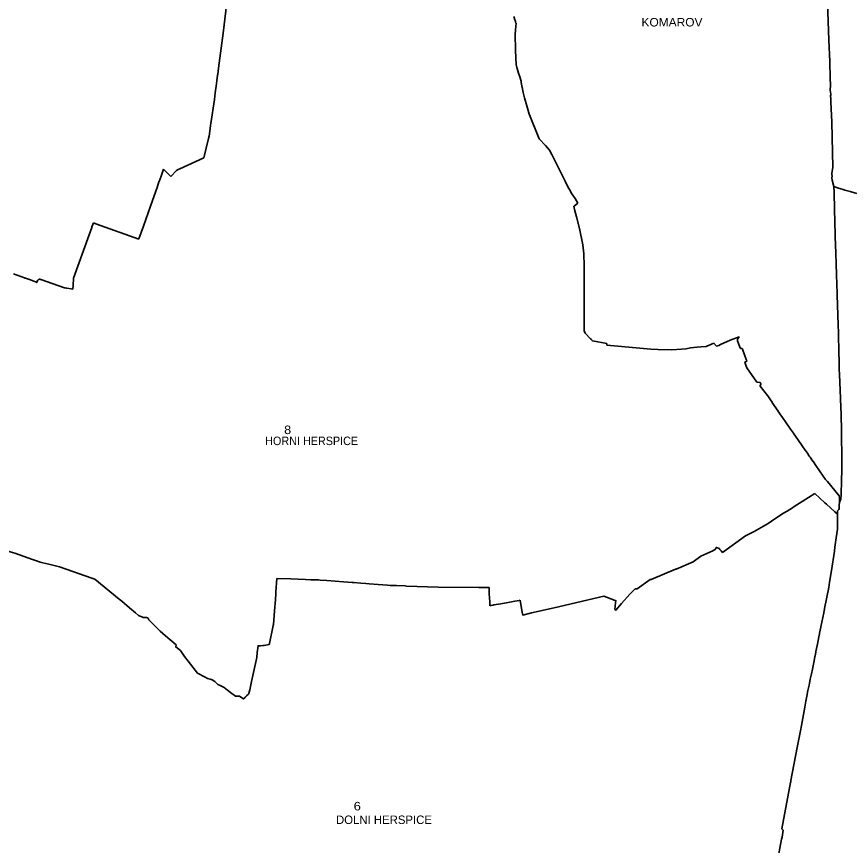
# Model space of a CAD drawing. Extents: x -610940 to -588976, y -1170376 to -1149800.
# Drawn here: x -599073 to -596623, y -1165505 to -1163066 of the extents above; entities that cross this region are included whole.
import ezdxf

# ---------------------------------------------------------------- set-up
doc = ezdxf.new("R2010")
doc.units = 0
doc.header["$LTSCALE"] = 10
doc.layers.add('54', color=7, linetype='Continuous', lineweight=35)
doc.layers.add('55', color=7, linetype='Continuous')
doc.layers.add('56', color=7, linetype='Continuous')

msp = doc.modelspace()

# ---------------------------------------------------------------- linework, layer by layer
at = {"layer": '54'}
for p, q in [((-598464.95, -1163115.09), (-598451.06, -1162998.14)), ((-597610.45, -1163066.2), (-597609.87, -1163066.21)), ((-597608.07, -1163072.05), (-597607.83, -1163072.91)), ((-597607.83, -1163072.91), (-597605.66, -1163080.64)), ((-597605.66, -1163080.64), (-597605.4, -1163081.55)), ((-597605.4, -1163081.55), (-597604.37, -1163085.24)), ((-597605.2, -1163105.32), (-597605.35, -1163106.86)), ((-597603.42, -1163085.32), (-597605.2, -1163105.32)), ((-597604.37, -1163085.24), (-597603.42, -1163085.32)), ((-598478.98, -1163217.84), (-598464.95, -1163115.09)), ((-597606.11, -1163121.9), (-597605.28, -1163160.73)), ((-597605.35, -1163106.86), (-597605.93, -1163117.82)), ((-597605.28, -1163160.73), (-597604.13, -1163191.12)), ((-598481.46, -1163235.41), (-598478.98, -1163217.84)), ((-597603.18, -1163206.85), (-597601.44, -1163215.82)), ((-598484, -1163254.75), (-598481.94, -1163238.29)), ((-598481.94, -1163238.29), (-598481.46, -1163235.41)), ((-598488.64, -1163290.22), (-598486.29, -1163271.01)), ((-598486.29, -1163271.01), (-598484, -1163254.75)), ((-597589.03, -1163256.49), (-597588.54, -1163259.21)), ((-597585.35, -1163274.68), (-597584.88, -1163276.98)), ((-597584.88, -1163276.98), (-597584.27, -1163279.87)), ((-598491.27, -1163310.15), (-598489.97, -1163300.3)), ((-598489.97, -1163300.3), (-598488.64, -1163290.22)), ((-597583.3, -1163284.56), (-597584.27, -1163279.87)), ((-597579.79, -1163301.44), (-597578.8, -1163305.33)), ((-598501.56, -1163380.59), (-598491.27, -1163310.15)), ((-597578.8, -1163305.33), (-597572.1, -1163328.68)), ((-596678.04, -1163304.09), (-596677.75, -1163309.5)), ((-596677.81, -1163310.4), (-596677.75, -1163309.5)), ((-597566.27, -1163349.51), (-597572.1, -1163328.68)), ((-597566.27, -1163349.51), (-597565.9, -1163350.64)), ((-597565.9, -1163350.64), (-597535.38, -1163425.53)), ((-598505.03, -1163403.24), (-598502.4, -1163386.35)), ((-598502.4, -1163386.35), (-598501.56, -1163380.59)), ((-596674.64, -1163376.76), (-596671.47, -1163509.45)), ((-598508.77, -1163424.6), (-598507.04, -1163418.39)), ((-598507.04, -1163418.39), (-598505.03, -1163403.24)), ((-598522.56, -1163481.75), (-598508.77, -1163424.6)), ((-597535.38, -1163425.53), (-597516.67, -1163445.76)), ((-597504.85, -1163459.04), (-597516.67, -1163445.76)), ((-597497.98, -1163472.09), (-597504.85, -1163459.04)), ((-597497.98, -1163472.09), (-597486.3, -1163495.56)), ((-598545.49, -1163492.33), (-598522.56, -1163481.75)), ((-597486.3, -1163495.56), (-597464.52, -1163540.2)), ((-598646.28, -1163530.12), (-598640.63, -1163515.36)), ((-598640.63, -1163515.36), (-598619.35, -1163536.58)), ((-598618.88, -1163537.07), (-598602.98, -1163518.68)), ((-598602.98, -1163518.68), (-598598.11, -1163516.34)), ((-596671.47, -1163509.45), (-596674.41, -1163528.15)), ((-598653.94, -1163551.52), (-598648.29, -1163535.64)), ((-598648.29, -1163535.64), (-598646.28, -1163530.12)), ((-598619.35, -1163536.58), (-598618.88, -1163537.07)), ((-597464.52, -1163540.2), (-597459.45, -1163550.45)), ((-596674.41, -1163528.15), (-596674.86, -1163531.03)), ((-598673.42, -1163606.84), (-598659.98, -1163568.74)), ((-597459.45, -1163550.45), (-597450.39, -1163568.8)), ((-597450.39, -1163568.8), (-597446.72, -1163574.98)), ((-596673.24, -1163547.39), (-596668.6, -1163566.25)), ((-596668.6, -1163566.25), (-596668.22, -1163582.88)), ((-596668.22, -1163582.88), (-596668.13, -1163584.57)), ((-596668.13, -1163584.57), (-596666.97, -1163633.07)), ((-598679.38, -1163623.84), (-598673.42, -1163606.84)), ((-597421.74, -1163615.53), (-597430.2, -1163601.79)), ((-598700.18, -1163683.1), (-598679.38, -1163623.84)), ((-597434.07, -1163624.47), (-597432.2, -1163633.39)), ((-597432.2, -1163633.39), (-597425.98, -1163655.84)), ((-596665.16, -1163708.42), (-596666.97, -1163633.07)), ((-597425.98, -1163655.84), (-597416.63, -1163689.87)), ((-598860.02, -1163708.78), (-598852.23, -1163687.24)), ((-598852.23, -1163687.24), (-598851.59, -1163684.53)), ((-598847.25, -1163673.21), (-598840.45, -1163675.63)), ((-598840.45, -1163675.63), (-598713.25, -1163720.79)), ((-598713.16, -1163720.23), (-598700.18, -1163683.1)), ((-597416.63, -1163689.87), (-597406.88, -1163737.46)), ((-598905.49, -1163835.95), (-598860.02, -1163708.78)), ((-596665.16, -1163708.42), (-596665.06, -1163709.74)), ((-596665.06, -1163709.74), (-596664.94, -1163713.24)), ((-596663.18, -1163762.77), (-596664.94, -1163713.24)), ((-598713.25, -1163720.79), (-598713.24, -1163720.45)), ((-598713.24, -1163720.45), (-598713.16, -1163720.23)), ((-597406.88, -1163737.46), (-597403.85, -1163764.64)), ((-596663.18, -1163762.77), (-596662.24, -1163793.77)), ((-596661.25, -1163826.12), (-596662.24, -1163793.77)), ((-599082.01, -1163822.83), (-599049.43, -1163834.91)), ((-599049.43, -1163834.91), (-599047.53, -1163835.59)), ((-599047.53, -1163835.59), (-599046.95, -1163835.78)), ((-599046.95, -1163835.78), (-599035.52, -1163840.08)), ((-599035.52, -1163840.08), (-599027.04, -1163843.24)), ((-599009.5, -1163840.54), (-599010.09, -1163841.02)), ((-599009.5, -1163840.54), (-599008.3, -1163839.82)), ((-599006.97, -1163839.35), (-599008.3, -1163839.82)), ((-599004.94, -1163839.17), (-599005.59, -1163839.16)), ((-599004.18, -1163839.25), (-599004.94, -1163839.17)), ((-599004.18, -1163839.25), (-599003.64, -1163839.38)), ((-599003.64, -1163839.38), (-599002.23, -1163839.87)), ((-599002.23, -1163839.87), (-598932.17, -1163864.39)), ((-598906.77, -1163857.59), (-598905.49, -1163835.95)), ((-596661.25, -1163826.12), (-596659.22, -1163880.6)), ((-599027.04, -1163843.24), (-599025.29, -1163843.93)), ((-599025.29, -1163843.93), (-599014.65, -1163847.95)), ((-599013.55, -1163848.36), (-599011.38, -1163842.61)), ((-599011.38, -1163842.61), (-599010.56, -1163841.5)), ((-599010.09, -1163841.02), (-599010.56, -1163841.5)), ((-598930.64, -1163864.62), (-598932.17, -1163864.39)), ((-598926.59, -1163865.26), (-598930.64, -1163864.62)), ((-598926.59, -1163865.26), (-598925.08, -1163865.5)), ((-598907.5, -1163868.46), (-598906.77, -1163857.59)), ((-598925.08, -1163865.5), (-598912.69, -1163867.58)), ((-598912.69, -1163867.58), (-598907.5, -1163868.46)), ((-596659.05, -1163885.1), (-596659.22, -1163880.6)), ((-596659.05, -1163885.1), (-596655.89, -1163973.84)), ((-596655.89, -1163973.84), (-596655.1, -1163995.95)), ((-597397.03, -1164000.7), (-597387.67, -1164011.18)), ((-597384.83, -1164014.36), (-597387.67, -1164011.18)), ((-596974.23, -1164018.09), (-596947.48, -1164008.55)), ((-596949.67, -1164011.76), (-596951.54, -1164014.29)), ((-596948.67, -1164010.82), (-596949.67, -1164011.76)), ((-596947.05, -1164010.14), (-596948.67, -1164010.82)), ((-596947.48, -1164008.55), (-596947.05, -1164010.14)), ((-596655.1, -1163995.95), (-596653.76, -1164058.59)), ((-597384.83, -1164014.36), (-597382.04, -1164016.6)), ((-597378.98, -1164019.93), (-597336.45, -1164028.3)), ((-597336.45, -1164028.3), (-597336.93, -1164033.18)), ((-597336.93, -1164033.18), (-597293.66, -1164036.95)), ((-597044.52, -1164036.95), (-597040.78, -1164035.05)), ((-597040.78, -1164035.05), (-597037.83, -1164033.81)), ((-597037.83, -1164033.81), (-597021.54, -1164027.3)), ((-597021.54, -1164027.3), (-597013.81, -1164036.15)), ((-597013.81, -1164036.15), (-597007.29, -1164033.59)), ((-597007.29, -1164033.59), (-597002.11, -1164031.53)), ((-597002.11, -1164031.53), (-596974.23, -1164018.09)), ((-596951.54, -1164014.29), (-596952.26, -1164016.82)), ((-596952.26, -1164016.82), (-596952.05, -1164019.96)), ((-596952.05, -1164019.96), (-596945.99, -1164035.92)), ((-596945.99, -1164035.92), (-596943.53, -1164042.42)), ((-597207.56, -1164044.46), (-597293.66, -1164036.95)), ((-597207.56, -1164044.46), (-597186.97, -1164045.74)), ((-597186.97, -1164045.74), (-597145.41, -1164047.21)), ((-597145.41, -1164047.21), (-597117.24, -1164045.29)), ((-597117.24, -1164045.29), (-597103.49, -1164043.65)), ((-597103.49, -1164043.65), (-597090.11, -1164041.16)), ((-597090.11, -1164041.16), (-597070.39, -1164039.36)), ((-597070.39, -1164039.36), (-597059.78, -1164038.36)), ((-597059.78, -1164038.36), (-597044.52, -1164036.95)), ((-596943.53, -1164042.42), (-596942.29, -1164042.95)), ((-596940.81, -1164043.22), (-596942.29, -1164042.95)), ((-596938.16, -1164042.93), (-596936.66, -1164047.11)), ((-596936.66, -1164047.11), (-596936.57, -1164047.36)), ((-596936.57, -1164047.36), (-596926.77, -1164074.84)), ((-596653.76, -1164058.59), (-596653.65, -1164063.91)), ((-596926.77, -1164074.84), (-596926.57, -1164075.38)), ((-596926.57, -1164075.38), (-596926.17, -1164076.47)), ((-596926.17, -1164076.47), (-596925.01, -1164079.73)), ((-596925.01, -1164079.73), (-596924.59, -1164080.65)), ((-596653.65, -1164063.91), (-596653.51, -1164070.29)), ((-596652.89, -1164099.41), (-596653.51, -1164070.29)), ((-596926.55, -1164094.4), (-596925.05, -1164099.48)), ((-596925.05, -1164099.48), (-596924.81, -1164100.05)), ((-596924.81, -1164100.05), (-596895.73, -1164142.25)), ((-596652.89, -1164099.41), (-596652.82, -1164104.17)), ((-596652.82, -1164104.17), (-596652.19, -1164119.57)), ((-596652.19, -1164119.57), (-596650.32, -1164165.33)), ((-596885.9, -1164143.39), (-596883.94, -1164146.41)), ((-596883.1, -1164147.7), (-596885.86, -1164152.86)), ((-596885.86, -1164152.86), (-596885.1, -1164153.84)), ((-596885.1, -1164153.84), (-596863.54, -1164181.64)), ((-596883.94, -1164146.41), (-596883.1, -1164147.7)), ((-596863.54, -1164181.64), (-596863.3, -1164182.04)), ((-596863.3, -1164182.04), (-596855.34, -1164193.92)), ((-596648.26, -1164215.64), (-596650.32, -1164165.33)), ((-596850.49, -1164201.15), (-596855.34, -1164193.92)), ((-596848.06, -1164204.67), (-596835.27, -1164223.72)), ((-596835.27, -1164223.72), (-596834.91, -1164224.38)), ((-596830.62, -1164230.54), (-596827.25, -1164235.38)), ((-596648.26, -1164215.64), (-596647.64, -1164235.73)), ((-596819.69, -1164246.24), (-596827.25, -1164235.38)), ((-596819.69, -1164246.24), (-596808.74, -1164261.95)), ((-596646.11, -1164285.72), (-596647.64, -1164235.73)), ((-596800.23, -1164274.17), (-596808.74, -1164261.95)), ((-596800.23, -1164274.17), (-596799.78, -1164274.8)), ((-596796.11, -1164280.08), (-596799.78, -1164274.8)), ((-596787.65, -1164292.22), (-596796.11, -1164280.08)), ((-596787.65, -1164292.22), (-596786.75, -1164293.49)), ((-596786.75, -1164293.49), (-596786.55, -1164293.77)), ((-596774.92, -1164310.53), (-596786.55, -1164293.77)), ((-596646.11, -1164285.72), (-596645.82, -1164320.71)), ((-596774.92, -1164310.53), (-596772.55, -1164313.95)), ((-596753.35, -1164341.66), (-596772.55, -1164313.95)), ((-596645.82, -1164320.71), (-596645.73, -1164328.76)), ((-596645.73, -1164328.76), (-596645.72, -1164332.1)), ((-596753.35, -1164341.66), (-596752.29, -1164343.19)), ((-596752.29, -1164343.19), (-596746.64, -1164351.33)), ((-596746.64, -1164351.33), (-596741.04, -1164359.41)), ((-596645.72, -1164332.1), (-596645.65, -1164342.8)), ((-596645.65, -1164342.8), (-596645.58, -1164355.3)), ((-596738.63, -1164362.88), (-596741.04, -1164359.41)), ((-596738.63, -1164362.88), (-596734.77, -1164368.45)), ((-596734.08, -1164369.45), (-596734.77, -1164368.45)), ((-596734.08, -1164369.45), (-596728.95, -1164376.86)), ((-596728.95, -1164376.86), (-596721.9, -1164387.05)), ((-596645.36, -1164394.31), (-596645.58, -1164355.3)), ((-596700.06, -1164418.61), (-596721.9, -1164387.05)), ((-596645.42, -1164400.8), (-596646.08, -1164431.38)), ((-596645.42, -1164400.8), (-596645.38, -1164396.41)), ((-596645.36, -1164394.31), (-596645.38, -1164396.41)), ((-596693.41, -1164428.14), (-596700.06, -1164418.61)), ((-596693.41, -1164428.14), (-596687.88, -1164434.76)), ((-596687.88, -1164434.76), (-596652.65, -1164476.04)), ((-596646.08, -1164431.38), (-596647.25, -1164472.71)), ((-596652.65, -1164476.04), (-596652.32, -1164481.2)), ((-596647.25, -1164472.71), (-596648.33, -1164485.17)), ((-596665.43, -1164523.87), (-596690.5, -1164501.09)), ((-596652.32, -1164481.2), (-596652.26, -1164484.33)), ((-596652.26, -1164484.33), (-596651.8, -1164496.45)), ((-596648.33, -1164485.17), (-596651.8, -1164496.45)), ((-596657.94, -1164530.67), (-596665.43, -1164523.87)), ((-596818.33, -1164528.9), (-596851.73, -1164551.25)), ((-596851.73, -1164551.25), (-596861.95, -1164558.24)), ((-596661.72, -1164599.63), (-596658.41, -1164574.75)), ((-596917.32, -1164588.71), (-596928.67, -1164594.51)), ((-596662.7, -1164607), (-596661.72, -1164599.63)), ((-596665.46, -1164627.69), (-596662.7, -1164607)), ((-597014.98, -1164628.16), (-597016.03, -1164630.5)), ((-597014.98, -1164628.16), (-597013.54, -1164628.7)), ((-597011.7, -1164629.4), (-597013.54, -1164628.7)), ((-597011.03, -1164629.65), (-597011.7, -1164629.4)), ((-597006.5, -1164631.23), (-597011.03, -1164629.65)), ((-597005.32, -1164632.63), (-597006.5, -1164631.23)), ((-598995.55, -1164673.37), (-599004.16, -1164671.33)), ((-598995.55, -1164673.37), (-598978.58, -1164677.4)), ((-597134.21, -1164692.44), (-597206.67, -1164723.2)), ((-597132.96, -1164691.88), (-597134.21, -1164692.44)), ((-598307.14, -1164719.42), (-598310.1, -1164758.69)), ((-598266.46, -1164720.98), (-598307.14, -1164719.42)), ((-598222.99, -1164722.65), (-598266.46, -1164720.98)), ((-598207.02, -1164723.24), (-598222.99, -1164722.65)), ((-598184.6, -1164724.07), (-598207.02, -1164723.24)), ((-598180.13, -1164724.23), (-598184.6, -1164724.07)), ((-598180.13, -1164724.23), (-598160.51, -1164725.74)), ((-598086.02, -1164731.49), (-598110.88, -1164729.57)), ((-598080.51, -1164731.91), (-598086.02, -1164731.49)), ((-598035.86, -1164735.36), (-598045.93, -1164734.59)), ((-598009.38, -1164737.41), (-598035.86, -1164735.36)), ((-597982.01, -1164739.53), (-598009.38, -1164737.41)), ((-597974.39, -1164740.12), (-597982.01, -1164739.53)), ((-597929.91, -1164741.78), (-597926.44, -1164741.91)), ((-597832.61, -1164745.4), (-597926.44, -1164741.91)), ((-597712.82, -1164746.39), (-597832.61, -1164745.4)), ((-597682.37, -1164765.09), (-597681.23, -1164788.12)), ((-597269.08, -1164765.54), (-597253.27, -1164750.63)), ((-597252.32, -1164749.73), (-597253.27, -1164750.63)), ((-597680.65, -1164799.86), (-597681.23, -1164788.12)), ((-597345.69, -1164771.82), (-597491.8, -1164806.11)), ((-596727.96, -1164966.91), (-596725.79, -1164956.26)), ((-596740.6, -1165029.12), (-596737.99, -1165015.77)), ((-598476.51, -1165034.06), (-598481.32, -1165031.92)), ((-598462.14, -1165040.47), (-598476.51, -1165034.06)), ((-598461.99, -1165040.58), (-598462.14, -1165040.47)), ((-598452.19, -1165048.16), (-598461.99, -1165040.58)), ((-598382.03, -1165022.88), (-598387.41, -1165047.87)), ((-596744.78, -1165049.48), (-596741.5, -1165033.61)), ((-596741.5, -1165033.61), (-596741.26, -1165032.46)), ((-596741.26, -1165032.46), (-596740.6, -1165029.12)), ((-598443.48, -1165054.9), (-598452.19, -1165048.16)), ((-598388.91, -1165054.81), (-598387.41, -1165047.87)), ((-596795.12, -1165314.79), (-596781.52, -1165242.76)), ((-596795.75, -1165318.12), (-596795.12, -1165314.79)), ((-596822.46, -1165487.36), (-596821.26, -1165480.96)), ((-596821.26, -1165480.96), (-596817.46, -1165460.54))]:
    msp.add_line(p, q, dxfattribs=at)
for points in [[(-596687.89, -1163020.33), (-596686.23, -1163052.33), (-596683.3, -1163135.1), (-596680.9, -1163198.37), (-596679.16, -1163247.31), (-596678.92, -1163268.24), (-596679.09, -1163282.17), (-596678.08, -1163294.51), (-596677.94, -1163295.97), (-596678.27, -1163299.43), (-596678.24, -1163301.44), (-596678.13, -1163303.2), (-596678.04, -1163304.09)], [(-597609.87, -1163066.21), (-597608.24, -1163071.5), (-597608.07, -1163072.05)], [(-597605.93, -1163117.82), (-597606.02, -1163119.8), (-597606.11, -1163121.9)], [(-597604.13, -1163191.12), (-597603.38, -1163203.61), (-597603.18, -1163206.85)], [(-597601.44, -1163215.82), (-597600.47, -1163219.15), (-597596.58, -1163232.53)], [(-597596.58, -1163232.53), (-597593.04, -1163243.76), (-597589.74, -1163253.48)], [(-597589.74, -1163253.48), (-597589.1, -1163256.18), (-597589.03, -1163256.49)], [(-597588.54, -1163259.21), (-597588.41, -1163259.83), (-597585.35, -1163274.68)], [(-597583.3, -1163284.56), (-597582.38, -1163289.13), (-597579.79, -1163301.44)], [(-596677.81, -1163310.4), (-596677.64, -1163311.74), (-596677.56, -1163314.85), (-596677.53, -1163316.66), (-596674.64, -1163376.76)], [(-598598.11, -1163516.34), (-598592.65, -1163513.86), (-598545.49, -1163492.33)], [(-596674.86, -1163531.03), (-596674.06, -1163535.9), (-596674.98, -1163540.33), (-596673.24, -1163547.39)], [(-598659.98, -1163568.74), (-598654.27, -1163552.46), (-598653.94, -1163551.52)], [(-596668.6, -1163566.25), (-596666.1, -1163567.3), (-596657.88, -1163569.87), (-596647.96, -1163572.99), (-596640.9, -1163575.2), (-596637.91, -1163576.14), (-596636.07, -1163576.71), (-596620.95, -1163580.82), (-596617.37, -1163581.79), (-596600.91, -1163586.27)], [(-597430.2, -1163601.79), (-597439.27, -1163587.35), (-597446.72, -1163574.98)], [(-597421.74, -1163615.53), (-597422.65, -1163616.19), (-597431.38, -1163622.52)], [(-597431.38, -1163622.52), (-597432.92, -1163623.64), (-597434.07, -1163624.47)], [(-598851.59, -1163684.53), (-598848.94, -1163677.63), (-598847.25, -1163673.21)], [(-597402.83, -1163821.07), (-597403.19, -1163799.44), (-597403.85, -1163764.64)], [(-599006.97, -1163839.35), (-599006.61, -1163839.28), (-599005.59, -1163839.16)], [(-597402.83, -1163821.07), (-597403.07, -1163868.98), (-597403.31, -1163917.99)], [(-599013.55, -1163848.36), (-599014.12, -1163848.15), (-599014.65, -1163847.95)], [(-597403.31, -1163917.99), (-597403.35, -1163926.54), (-597403.5, -1163955.41), (-597403.54, -1163964.52)], [(-597403.67, -1163990.59), (-597403.65, -1163986.77), (-597403.62, -1163980.56), (-597403.54, -1163964.52)], [(-597400.06, -1163997.31), (-597403.26, -1163991.35), (-597403.67, -1163990.59)], [(-597400.06, -1163997.31), (-597397.93, -1163999.7), (-597397.03, -1164000.7)], [(-597382.04, -1164016.6), (-597381.66, -1164017.16), (-597379.86, -1164019.76), (-597378.98, -1164019.93)], [(-596940.81, -1164043.22), (-596939.44, -1164043.21), (-596938.16, -1164042.93)], [(-596926.55, -1164094.4), (-596930.17, -1164082.74), (-596924.59, -1164080.65)], [(-596885.9, -1164143.39), (-596886.52, -1164142.6), (-596895.73, -1164142.25)], [(-596848.06, -1164204.67), (-596848.74, -1164203.67), (-596850.05, -1164201.72), (-596850.49, -1164201.15)], [(-596834.91, -1164224.38), (-596831.73, -1164228.94), (-596830.62, -1164230.54)], [(-596725.15, -1164469.62), (-596762.03, -1164493.17), (-596769.98, -1164498.28), (-596785.42, -1164508.07), (-596790.67, -1164511.37), (-596806.36, -1164521.37), (-596818.33, -1164528.9)], [(-596725.15, -1164469.62), (-596709.56, -1164483.78), (-596694.92, -1164497.08), (-596690.5, -1164501.09)], [(-596657.94, -1164530.67), (-596657.95, -1164528.31), (-596657.91, -1164520.29), (-596653.59, -1164516.68), (-596653.48, -1164513.4), (-596652.62, -1164500.02), (-596652.5, -1164499.1), (-596651.8, -1164496.45)], [(-596658.41, -1164574.75), (-596658.37, -1164570.86), (-596658.13, -1164548.75), (-596657.94, -1164530.67)], [(-596861.95, -1164558.24), (-596903.58, -1164581.69), (-596917.32, -1164588.71)], [(-596928.67, -1164594.51), (-596996.01, -1164643.08), (-597000.57, -1164638.01), (-597004.13, -1164634.07), (-597005.32, -1164632.63)], [(-599004.16, -1164671.33), (-599014.4, -1164667.78), (-599026.76, -1164663.5), (-599078.58, -1164645.56), (-599091.98, -1164640.92), (-599118.71, -1164631.67)], [(-597024.76, -1164638.13), (-597060.45, -1164653.87), (-597082.48, -1164670.56), (-597132.96, -1164691.88)], [(-597016.03, -1164630.5), (-597018.09, -1164634.4), (-597023.51, -1164637.49), (-597024.76, -1164638.13)], [(-596725.79, -1164956.26), (-596724.46, -1164949.67), (-596724.01, -1164947.43), (-596721.8, -1164936.47), (-596721.46, -1164934.78), (-596716.07, -1164908.01), (-596715.8, -1164906.7), (-596711.8, -1164886.83), (-596711.59, -1164885.8), (-596711.3, -1164884.37), (-596711.04, -1164883.06), (-596710.5, -1164880.39), (-596707.01, -1164863.06), (-596706.8, -1164862.02), (-596698.54, -1164820.94), (-596698.26, -1164819.57), (-596696.38, -1164810.22), (-596695.99, -1164808.28), (-596683.45, -1164745.95), (-596681.09, -1164730.88), (-596675.62, -1164695.94), (-596667.01, -1164639.37), (-596665.46, -1164627.69)], [(-598842.63, -1164722.2), (-598851.58, -1164719.11), (-598946.48, -1164685.02), (-598978.58, -1164677.4)], [(-598705.13, -1164832.56), (-598714.06, -1164828.92), (-598723.53, -1164820.38), (-598740.56, -1164806.23), (-598763.62, -1164786.92), (-598771.73, -1164780.23), (-598842.63, -1164722.2)], [(-598160.51, -1164725.74), (-598135.95, -1164727.64), (-598110.88, -1164729.57)], [(-598080.51, -1164731.91), (-598060.39, -1164733.47), (-598045.93, -1164734.59)], [(-597974.39, -1164740.12), (-597955.18, -1164740.84), (-597929.91, -1164741.78)], [(-597683.28, -1164746.64), (-597698.45, -1164746.51), (-597702.13, -1164746.48), (-597709.83, -1164746.42), (-597712.82, -1164746.39)], [(-597683.28, -1164746.64), (-597683.11, -1164750.13), (-597682.96, -1164753.09), (-597682.37, -1164765.09)], [(-597206.67, -1164723.2), (-597209.32, -1164722.84), (-597247.76, -1164750.13), (-597252.32, -1164749.73)], [(-598310.1, -1164758.69), (-598310.78, -1164767.9), (-598311.58, -1164778.75), (-598311.79, -1164782.11), (-598312.62, -1164793.18), (-598313.46, -1164803.62)], [(-597269.08, -1164765.54), (-597293.27, -1164793.49), (-597309.98, -1164812.63), (-597313.22, -1164810.91), (-597311.56, -1164791.34), (-597309.84, -1164785.25), (-597311.64, -1164784.58), (-597337.62, -1164774.84), (-597345.69, -1164771.82)], [(-597591.39, -1164783.88), (-597593.08, -1164784.12), (-597607.53, -1164786.81), (-597621.85, -1164789.42), (-597648.9, -1164794.17), (-597668.64, -1164797.48), (-597671.14, -1164797.97), (-597677.57, -1164799.24), (-597680.65, -1164799.86)], [(-597588.52, -1164801.46), (-597591.34, -1164784.21), (-597591.39, -1164783.88)], [(-598313.46, -1164803.62), (-598317.45, -1164854.89), (-598318.08, -1164858.19), (-598329.31, -1164911.03), (-598330.37, -1164913.71), (-598344.33, -1164916.73), (-598348.45, -1164917.15), (-598355.68, -1164917.99), (-598362.45, -1164917.74), (-598365.51, -1164937.89), (-598366.46, -1164951.89), (-598382.03, -1165022.88)], [(-597491.8, -1164806.11), (-597558, -1164821.27), (-597584.19, -1164827.26), (-597585.62, -1164819.36), (-597588.47, -1164801.78), (-597588.52, -1164801.46)], [(-598635.08, -1164888.83), (-598651.19, -1164874.82), (-598683.6, -1164841.27), (-598687.51, -1164835.73), (-598690.86, -1164834.1), (-598691.75, -1164834.21), (-598699.56, -1164834.63), (-598700.01, -1164834.66), (-598700.55, -1164834.44), (-598705.13, -1164832.56)], [(-598568.1, -1164962.95), (-598578.88, -1164949.05), (-598590.99, -1164931.34), (-598604.79, -1164921.03), (-598603.75, -1164915.37), (-598635.08, -1164888.83)], [(-598481.32, -1165031.92), (-598489.67, -1165022.89), (-598497.45, -1165017.8), (-598504.12, -1165016.32), (-598511.08, -1165014.52), (-598518.52, -1165010.58), (-598540.77, -1164998.62), (-598568.1, -1164962.95)], [(-596737.99, -1165015.77), (-596734.82, -1165000.39), (-596731.92, -1164986.67), (-596728.99, -1164971.98), (-596727.96, -1164966.91)], [(-598388.91, -1165054.81), (-598389.53, -1165057.72), (-598389.61, -1165058.08), (-598390.52, -1165059.95), (-598395.55, -1165064.55), (-598397.35, -1165066.36), (-598397.71, -1165066.74), (-598398.26, -1165067.22), (-598400.2, -1165069.16), (-598401.78, -1165070.7), (-598405.61, -1165074.41), (-598405.96, -1165074.76), (-598407.77, -1165073.32), (-598417.26, -1165066.27), (-598429.36, -1165065.81), (-598443.48, -1165054.9)], [(-596781.52, -1165242.76), (-596775.77, -1165212.39), (-596767.13, -1165167.77), (-596764.18, -1165152.69), (-596754.26, -1165098.34), (-596750.86, -1165080.34), (-596748.25, -1165066.28), (-596744.78, -1165049.48)], [(-596817.46, -1165460.54), (-596822.14, -1165456.96), (-596796.22, -1165320.62), (-596795.75, -1165318.12)], [(-596868.16, -1165739.79), (-596858.93, -1165698.74), (-596856.01, -1165677.98), (-596852.77, -1165655.83), (-596851.51, -1165644.6), (-596850.07, -1165633.81), (-596849.15, -1165622.27), (-596848.14, -1165606.08), (-596844.75, -1165593.81), (-596840.78, -1165579.41), (-596837.19, -1165566.42), (-596822.46, -1165487.36)]]:
    msp.add_lwpolyline(points, dxfattribs=at)

# ---------------------------------------------------------------- texts
at = {"layer": '55'}
for s, width, p in [('KOMAROV ', 1.05, (-597234.62, -1163095.14)), ('HORNI HERSPICE', 0.95, (-598341.81, -1164327.18))]:
    msp.add_text(s, height=25, dxfattribs=dict(at, width=width)).set_placement(p)
msp.add_text('DOLNI HERSPICE', height=25, dxfattribs=at).set_placement((-598133.47, -1165442.4))
at = {"layer": '56'}
for s, width, p in [('8 ', 1.1, (-598285.83, -1164294.73)), ('6 ', 1.15, (-598081.52, -1165402.31))]:
    msp.add_text(s, height=25, dxfattribs=dict(at, width=width)).set_placement(p)

doc.saveas('drawing.dxf')
